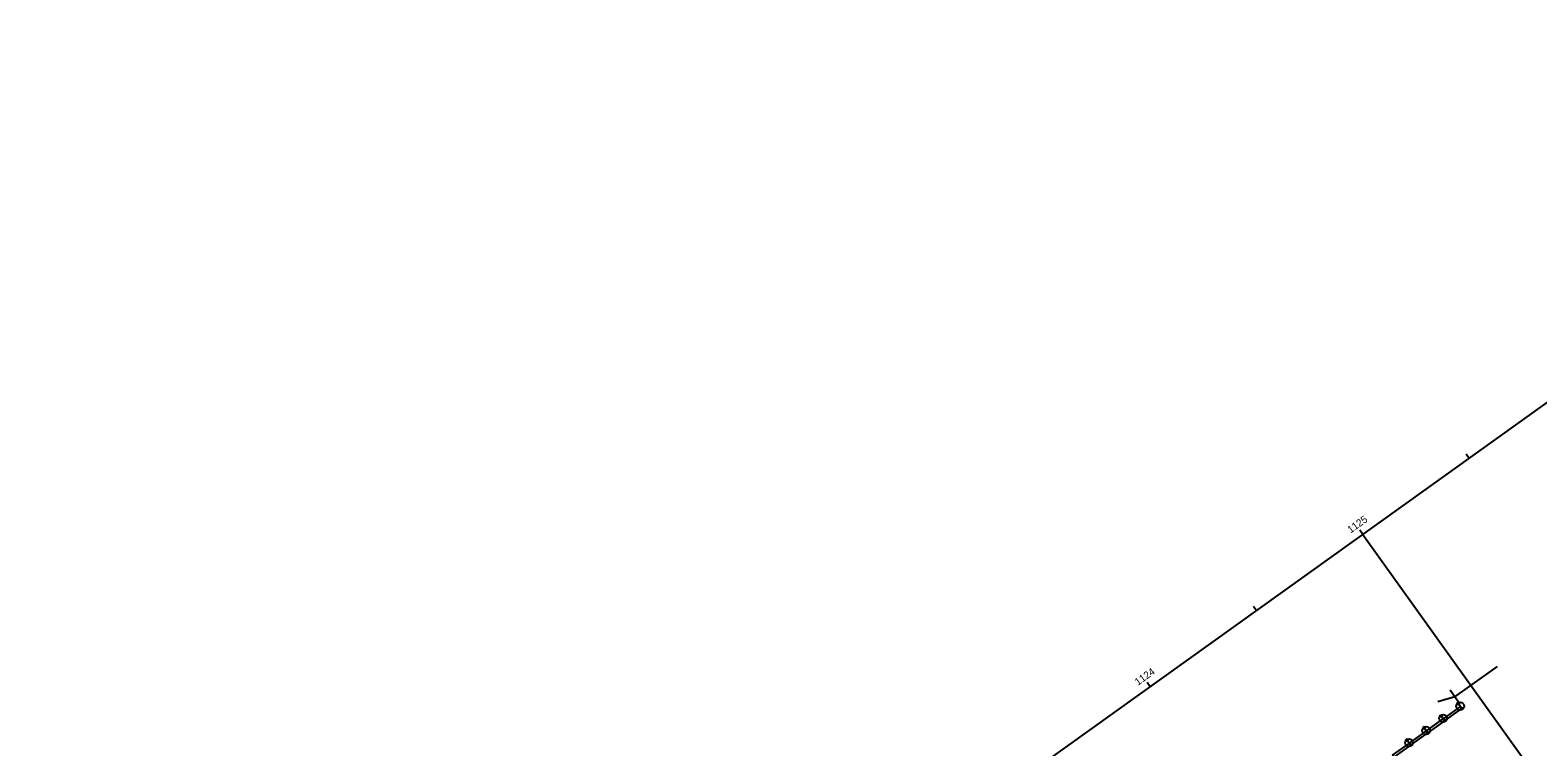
# Model space of a CAD drawing. Extents: x 2079879 to 2092887, y 778083 to 784051.
# Drawn here: x 2083885 to 2084461, y 781207 to 781481 of the extents above; entities that cross this region are included whole.
import ezdxf

# ---------------------------------------------------------------- set-up
doc = ezdxf.new("R2010")
doc.units = 0
for name, color, linetype in [('SC_Scratch1', 7, 'Continuous'), ('SH_Data', 7, 'Continuous'), ('SH_Text', 7, 'Continuous'), ('XS_X_Pavt', 7, 'Continuous')]:
    doc.layers.add(name, color=color, linetype=linetype)

msp = doc.modelspace()

# ---------------------------------------------------------------- linework, layer by layer
at = {"layer": 'SC_Scratch1'}
for p, q in [((2079923.52, 778084.44), (2085691.45, 782217.74)), ((2084434.8, 781317.22), (2084433.63, 781318.84)), ((2084394.15, 781288.09), (2084392.99, 781289.72)), ((2084353.51, 781258.97), (2084352.35, 781260.59)), ((2084312.87, 781229.84), (2084311.7, 781231.47))]:
    msp.add_line(p, q, dxfattribs=at)
at = {"layer": 'SH_Data'}
for p, q in [((2084394.15, 781288.09), (2084523.01, 781108.28)), ((2084429.29, 781226.07), (2084445.64, 781237.6)), ((2084431.02, 781223.62), (2084427.56, 781228.53)), ((2084429.29, 781226.07), (2084422.88, 781224.13)), ((2084430.68, 781223.38), (2084430.25, 781223.99)), ((2084417.68, 781214.06), (2084417.25, 781214.67)), ((2084411.18, 781209.4), (2084410.74, 781210.01))]:
    msp.add_line(p, q, dxfattribs=at)
at = {"layer": 'SH_Text'}
for centre in [(2084431.34, 781222.47), (2084424.83, 781217.81), (2084418.33, 781213.15), (2084411.83, 781208.49)]:
    msp.add_circle(centre, 1.5, dxfattribs=at)
at = {"layer": 'XS_X_Pavt'}
for points in [[(2084430.35, 781223.14), (2084431.02, 781223.62), (2084431.05, 781223.59), (2084430.73, 781223.37), (2084431.99, 781221.61), (2084432.31, 781221.83), (2084432.33, 781221.8), (2084431.65, 781221.32), (2084431.63, 781221.35), (2084431.94, 781221.57), (2084430.68, 781223.33), (2084430.37, 781223.1)], [(2084418.54, 781213), (2084424.91, 781217.56), (2084425.4, 781216.88), (2084419.03, 781212.32)], [(2084423.84, 781218.48), (2084424.52, 781218.96), (2084424.54, 781218.93), (2084424.23, 781218.71), (2084425.49, 781216.95), (2084425.8, 781217.17), (2084425.83, 781217.14), (2084425.15, 781216.66), (2084425.12, 781216.69), (2084425.44, 781216.91), (2084424.18, 781218.67), (2084423.87, 781218.44)], [(2084425.05, 781217.66), (2084431.41, 781222.22), (2084431.9, 781221.54), (2084425.53, 781216.98)], [(2084412.04, 781208.34), (2084418.41, 781212.9), (2084418.89, 781212.22), (2084412.53, 781207.66)], [(2084417.34, 781213.82), (2084418.02, 781214.3), (2084418.04, 781214.27), (2084417.73, 781214.05), (2084418.99, 781212.29), (2084419.3, 781212.51), (2084419.32, 781212.48), (2084418.65, 781212), (2084418.62, 781212.03), (2084418.94, 781212.25), (2084417.68, 781214.01), (2084417.36, 781213.79)], [(2084405.54, 781203.68), (2084411.91, 781208.24), (2084412.39, 781207.56), (2084406.02, 781203)], [(2084410.84, 781209.16), (2084411.51, 781209.64), (2084411.54, 781209.61), (2084411.23, 781209.39), (2084412.48, 781207.63), (2084412.8, 781207.85), (2084412.82, 781207.82), (2084412.14, 781207.34), (2084412.12, 781207.37), (2084412.43, 781207.59), (2084411.17, 781209.35), (2084410.86, 781209.13)]]:
    msp.add_lwpolyline(points, close=True, dxfattribs=at)

# ---------------------------------------------------------------- texts
at = {"layer": 'SC_Scratch1'}
for s, p in [('1125', (2084389.5, 781288.45)), ('1124', (2084308.24, 781230.22))]:
    msp.add_text(s, height=2.8, rotation=35.62538, dxfattribs=at).set_placement(p)

doc.saveas('drawing.dxf')
